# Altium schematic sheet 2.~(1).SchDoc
size 386 x 246 mm; Organization: Altium Limited; Address1: L3, 12a Rodborough Rd; Address2: Frenchs Forest; Address3: NSW; Address4: Australia 2086
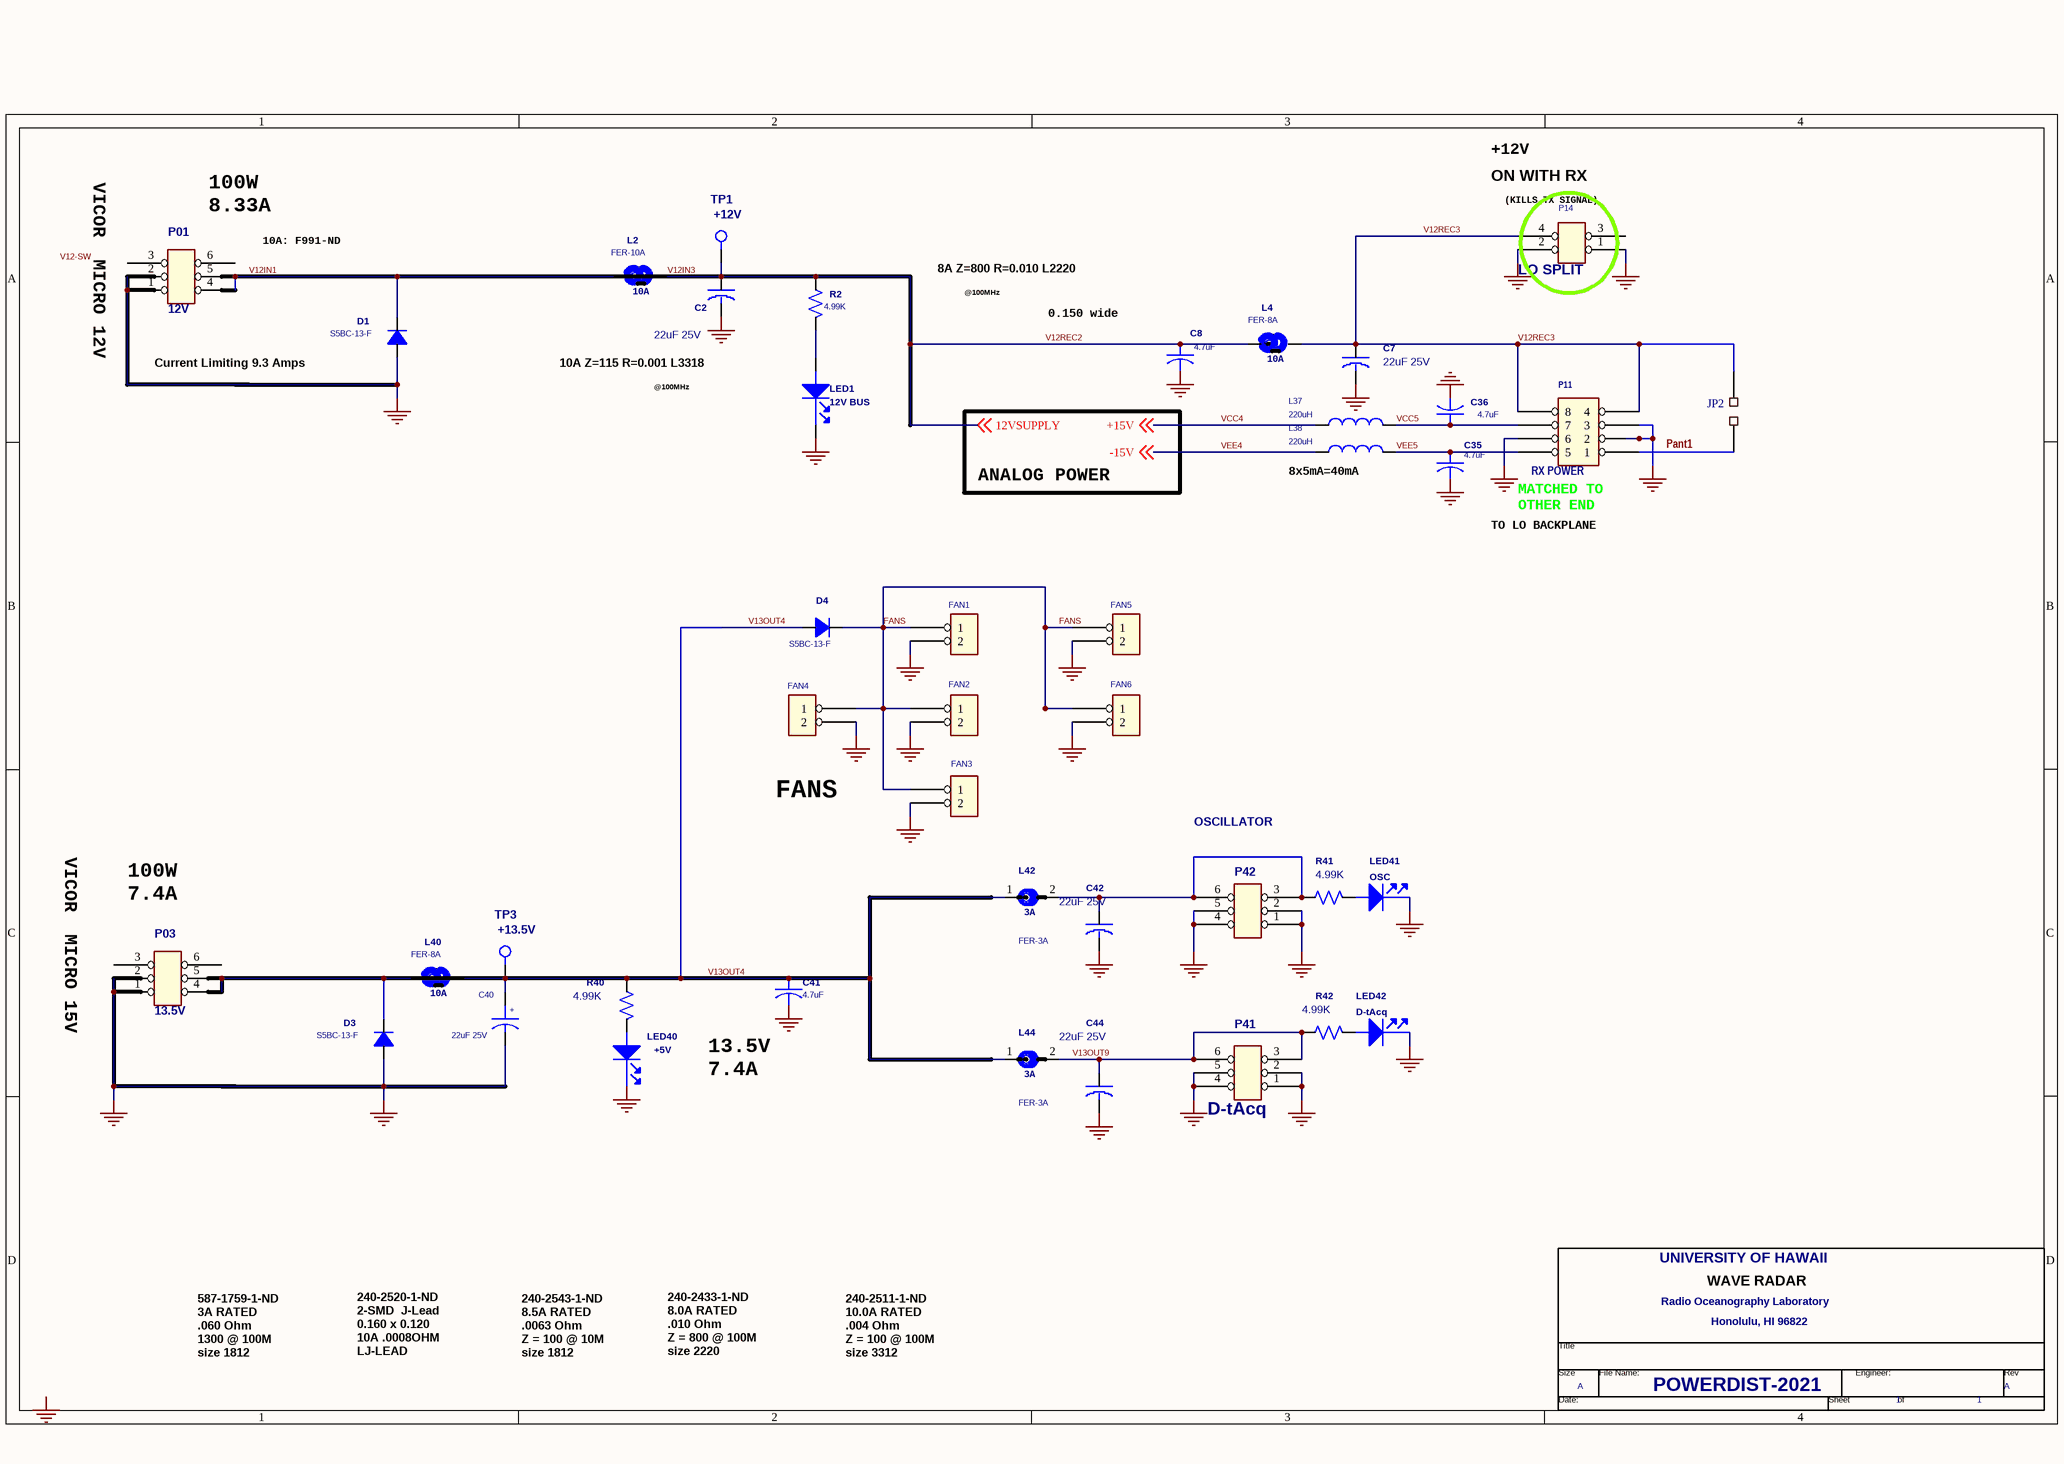
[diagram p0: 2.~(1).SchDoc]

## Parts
*  Doc: POWERDIST-2021  RevCode: A  OrgName: UNIVERSITY OF HAWAII  OrgAddr1: Radio Oceanography Laboratory  OrgAddr3: Honolulu, HI 96822  Page Number: 1  (hidden comment: HWRadar)  (graphical)
C2  22uF 25V  [1812]
C7  22uF 25V  [1812]
C8  4.7uF  [1812]
C35  4.7uF  [1812]
C36  4.7uF  [1812]
C40  22uF 25V  [1812]
C41  4.7uF  [1812]
C42  22uF 25V  [1812]
C44  22uF 25V  [1812]
D1  S5BC-13-F  [SMC]
D3  S5BC-13-F  [SMC]
D4  S5BC-13-F  [SMC]
FAN1  FAN1  [SIP2-SHRD]  (value not drawn)
FAN2  FAN2  [SIP2-SHRD]  (value not drawn)
FAN3  FAN3  [SIP2-SHRD]  (value not drawn)
FAN4  FAN4  [SIP2-SHRD]  (value not drawn)
FAN5  FAN1  [SIP2-SHRD]  (value not drawn)
FAN6  FAN2  [SIP2-SHRD]  (value not drawn)
JP2  (no value)  [2X2.54]
L2  FER-10A  [l3318]
L4  FER-8A  [2220]
L37  220uH  [1812]
L38  220uH  [1812]
L40  FER-8A  [2220]
L42  FER-3A  [1812]
L44  FER-3A  [1812]
LED1  12V BUS  [LED1206]
LED40  +5V  [LED1206]
LED41  D-tAcq  [LED1206]
LED42  OSC  [LED1206]
P01  12V  [MFTJR2X3]
P03  13.5V  [MFTJR2X3]
P11  RX POWER  [MFTJR2X4]
P14  LO SPLIT  [MFTJR2X2]
P41  D-tAcq  [MFTJR2X3]
P42  OSCILLATOR  [MFTJR2X3]
R2  4.99K  [1206]
R40  4.99K  [1206]
R41  4.99K  [1206]
R42  4.99K  [1206]
TP1  +12V  [TP]
TP3  +13.5V  [TP]

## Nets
GND: C2.2 C7.2 C8.2 C35.2 C36.2 C40.2 C41.2 C42.2 C44.2 D1.A(ANOD) D3.A(ANOD) FAN1.2 FAN2.2 FAN3.2 FAN4.2 FAN5.2 FAN6.2 LED1.2(CATHODE) LED40.2(CATHODE) LED41.2(CATHODE) LED42.2(CATHODE) P01.1 P01.2 P03.1 P03.2 P11.2 P11.3 P11.6 P14.1 P14.2 P41.1 P41.2 P41.4 P41.5 P42.1 P42.2 P42.4 P42.5
FANS: D4.K(CATH) FAN1.1 FAN2.1 FAN3.1 FAN4.1 FAN5.1 FAN6.1
Pant1: JP2.1 P11.1
V12IN1: D1.K(CATH) L2.1(L1) P01.4 P01.5
V12IN3: C2.1 C8.1 L2.2(L2) L4.1(L1) R2.1 TP1.TP ; off-sheet 12VSUPPLY  [also labelled 12VSUPPLY, V12REC2]
V12REC3: C7.1 JP2.2 L4.2(L2) P11.4 P11.8 P14.4
V13OUT4: C40.1 C41.1 D4.A(ANOD) L40.2(L2) L42.1(L1) L44.1(L1) R40.1 TP3.TP
V13OUT9: C44.1 L44.2(L2) P41.3 P41.6 R42.1
VCC4: L37.1 ; off-sheet +15V  [also labelled +15V]
VCC5: C36.1 L37.2 P11.7
VEE4: L38.1 ; off-sheet -15V  [also labelled -15V]
VEE5: C35.1 L38.2 P11.5
NetC42_1: C42.1 L42.2(L2) P42.3 P42.6 R41.1
NetD3_K: D3.K(CATH) L40.1(L1) P03.4 P03.5
NetLED1_1: LED1.1(ANODE) R2.2
NetLED40_1: LED40.1(ANODE) R40.2
NetLED41_1: LED41.1(ANODE) R41.2
NetLED42_1: LED42.1(ANODE) R42.2

Not connected (* = marked no-connect by the designer): P01 3 6; P03 3 6; P14 3

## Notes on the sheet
- +12V
- VICOR  MICRO 12V
- (near P01) 100W
  8.33A
- (near P14) ON WITH RX
- (near P14) (KILLS TX SIGNAL)
- 10A: F991-ND
- 8A Z=800 R=0.010 L2220
- @100MHz
- Current Limiting 9.3 Amps
- 10A Z=115 R=0.001 L3318
- 0.150 wide
- ANALOG POWER
- (near L38) 8x5mA=40mA
- TO LO BACKPLANE
- (near P11) MATCHED TO
  OTHER END
- FANS
- VICOR  MICRO 15V
- (near P03) 100W
  7.4A
- (near C41) 13.5V
  7.4A
- 587-1759-1-ND
  3A RATED
  .060 Ohm
  1300 @ 100M
  size 1812
- 240-2520-1-ND
  2-SMD  J-Lead
  0.160 x 0.120
  10A .0008OHM
  LJ-LEAD
- 240-2543-1-ND
  8.5A RATED
  .0063 Ohm
  Z = 100 @ 10M
  size 1812
- 240-2433-1-ND
  8.0A RATED
  .010 Ohm
  Z = 800 @ 100M
  size 2220
- 240-2511-1-ND
  10.0A RATED
  .004 Ohm
  Z = 100 @ 100M
  size 3312
- Labels drawn without touching a wire or pin: GND, V12-SW

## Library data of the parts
* = HWRadar: Engineer:: <ENG>; OrgAddr2: 2525 Correa Road
C2 C7 C42 C44 = C1206: DK Stock: 445-1607-1-ND
C8 C35 C36 C41 = CAP1206: DK Stock: 445-1446-1-ND
C40 = CAPACITOR POL: DK Stock: 445-1607-1-ND
D1 D3 D4 = DIODE2: DK Stock: S5BC-FDICT-ND
FAN1-FAN6 = HEADER 2_0: DK Stock: A30931-ND
JP2 = STRAP
L2 = FERRITE1812_0: DK Stock: 240-2511-1-ND
L4 L40 = FERRITE1812_0: DK Stock: 240-2433-1-ND
L37 L38 = INDUCTOR: DK Stock: DN7942CT-ND
L42 L44 = FERRITE_0: DK Stock: 587-1759-1-ND
LED1 = LED_1: DK Stock: 754-1445-1-ND
LED40-LED42 = LED_0: DK Stock: 754-1445-1-ND
P01 P03 P41 P42 = HEADER 3X2_0: DK Stock: WM3802-ND
P11 = HEADER 4X2_0: DK Stock: WM3803-ND
P14 = HEADER 2X2_5: DK Stock: WM3801-ND
R2 = RES1206: DK Stock: 311-4..99KFRCT-ND
R40-R42 = RES1206: DK Stock: 311-2.49KFRCT-ND
TP1 TP3 = TP: DK Stock: NS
